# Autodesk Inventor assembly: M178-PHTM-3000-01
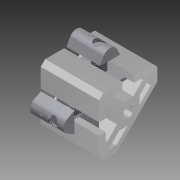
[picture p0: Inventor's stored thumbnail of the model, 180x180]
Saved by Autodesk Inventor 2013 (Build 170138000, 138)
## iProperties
Created: 2004-11
Part Number: M178-PHTM-3000-01
Document SubType Name: Assembly
Designer: Autodesk, Inc.
Manufacturer: Standard
Standards Organization: Custom
Description: PHANTOM, CORNER BRACKET 1
Mass: 135.093 g
Surface Area: 199.408 cm^2
Volume: 36.5928 cm^3
Density: 3.6918 g/cm^3
CAGE: 1LJX3
Dept. ID: Product Design
Description #2: ---
Finish #1: ---
Finish #2: ---
Material ID: ---
Project Number: ---
Author: Autodesk, Inc.
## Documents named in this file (6)
- Z:\_DATEN\Test Station\Components\21-135 Corner Phantom.iam
- Z:\_DATEN\Test Station\Components\21-135.ipt
- Z:\_DATEN\Test Station\Components\20-028.iam
- Z:\_DATEN\Test Station\Components\20-058.ipt
- C:\Users\kelleyb.ADS\Desktop\Samples MIGRATED 2009 224 RTM_1\Standard Parts\Test Station Content\Corners, Gussets, and Mounting Plates\21-XXX Corner Elements.ipt
- C:\Users\kelleyb.ADS\Desktop\Samples MIGRATED 2009 224 RTM_1\Standard Parts\Test Station Content\Fastners\20-XXX TSlot Nuts.ipt
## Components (5 placed, 3 different names)
1. 21-135:1 — Mate:3, Mate:4, Angle:2, Mate:7, Angle:4
2. 20-028:2 [sub-assembly] — Mate:3, Mate:4, Angle:2, Mate:6
3. 20-058:2 — Mate:6, Mate:7, Angle:4
4. 20-028:3 [sub-assembly]
5. 20-058:3
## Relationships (6: Mate 4, Angle 2)
- Mate:3: 21-135:1 ↔ 20-028:2
- Mate:4: 21-135:1 ↔ 20-028:2
- Angle:2: 21-135:1 ↔ 20-028:2
- Mate:6: 20-028:2 ↔ 20-058:2
- Mate:7: 21-135:1 ↔ 20-058:2
- Angle:4: 21-135:1 ↔ 20-058:2
